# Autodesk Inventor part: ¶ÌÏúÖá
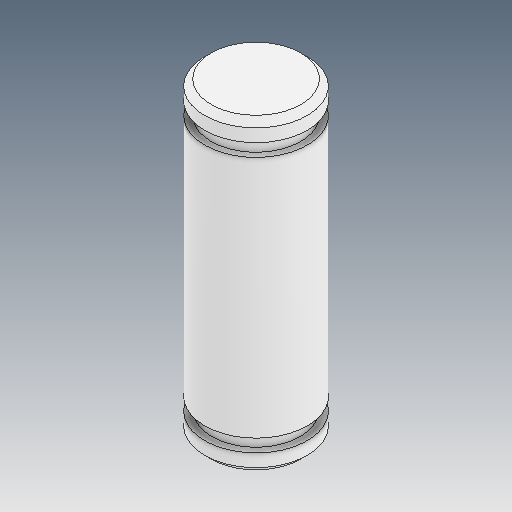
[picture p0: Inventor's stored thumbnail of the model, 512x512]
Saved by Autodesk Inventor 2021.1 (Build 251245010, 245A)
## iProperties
Created: 2021-05
Part Number: ¶ÌÏúÖá
Material: Ogólny
Document SubType Name: Modeling
Designer: user
Density: 1 g/cm^3
Appearance: Domyślna
Author: user
Revision Number: ÈÎºÎ
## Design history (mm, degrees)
feature "ÊäÈë1"
node "Bryła1"
